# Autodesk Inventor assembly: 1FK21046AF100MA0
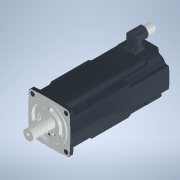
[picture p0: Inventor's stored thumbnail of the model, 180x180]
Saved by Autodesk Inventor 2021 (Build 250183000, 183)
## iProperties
Category: PARTsolutions
Created: 2026-06
Part Number: 1FK21046AF100MA0
Catalog Web Link: www.3dfindit.com
Description: 1FK21046AF100MA0-Servo synchronous motor
Document SubType Name: Assembly
Designer: psAdmin
Mass: 1063.44 g
Surface Area: 1248.48 cm^2
Volume: 1063.44 cm^3
Density: 1 g/cm^3
Title: 1FK21046AF100MA0
Author: Cadenas PARTsolutions
Comments: Servo synchronous motor
PSOL_IDENT_0: {$CADENAS_DATA/23d-libs/siemens_ag/_cat_/4f/2b/1fk21046af100ma0.prj},193 {STYP=ASS},{VTYP=3D},{NB=1F
PSOL_IDENT_1: K21046AF100MA0},{LINA=1FK21046AF100MA0},{NN=1FK21046AF100MA0},{DATE=19.08.2025 14:00:37},{GEOMDATE=3
PSOL_IDENT_2: 0.07.2025 02:01:06},{VERSION=},{LINEID=10},{WBVAR=},{WBNUMERIC=}  {NB=1FK21046AF100MA0},{LINA=1FK210
PSOL_IDENT_3: 46AF100MA0},{KT=DUMMY},{PREVIEW=../../../_pool_/cb/72/p_d211_xx_00434j.png},{DESCSHORT=SIMOTICS S-1F
PSOL_IDENT_4: K2 HD, SINAMICS S210 3AC 400V-480V, 3.2 Nm, 3000 rpm},{DESCLONG=SIMOTICS S-1FK2 HD servo motor M0=3.
PSOL_IDENT_5: 2 Nm; PN = 1 kW at nN=3000 rpm (380-480 V); PN = 0.5 kW at nN=1500 rpm (200-240 V); with holding bra
PSOL_IDENT_6: ke; degree of protection IP64; cylindrical shaft D19x40mm; absolute encoder 22-bit + 12-bit multitur
PSOL_IDENT_7: n (encoder AM22DQC); with OCC interface; plug size M17, rotatable; SIMOTICS S-1FK2 servomotorfor a w
PSOL_IDENT_8: ide range of uses in industrial environments. SIMOTICS S‑1FK2 servomotors are compact synchronous mo
PSOL_IDENT_9: tors with a high dynamic performance that set themselves apart as a result of their high power densi
PSOL_IDENT_10: ty, degree of protection and overload capability. The motors are available in two variants: as High
PSOL_IDENT_11: Dynamic variant (highest dynamic performance as a result of the low intrinsic moment of inertia for
PSOL_IDENT_12: applications demanding a high dynamic performance with low moved masses) - and as Compact variant (p
PSOL_IDENT_13: recise and stable closed-loop control for medium up to large moved masses as a result of a medium in
PSOL_IDENT_14: trinsic moment of inertia). SIMOTICSS‑1FK2 servomotors fully exploit their strengths in a system wit
PSOL_IDENT_15: h the SINAMICSS210 frequency converter and simple connection using the one cable connection (OCC). A
PSOL_IDENT_16: dvantages include the short control and positioning times, fast and precise correction of disturbing
PSOL_IDENT_17: quantities as well as stable control with a high dynamic performance. The servo motors can be confi
PSOL_IDENT_18: gured to address a wide range of requirements. For example with and without holding brake, IP64 or I
PSOL_IDENT_19: P65 degree of protection, singleturn or multiturn absolute encoders - to name just a few. Further, t
PSOL_IDENT_20: he servomotors are available in different shaft heights extending from 20 to 100. A shaft sealing ri
PSOL_IDENT_21: ng is available to achieve an IP65 degree of protection and for subsequent mounting at the motor or
PSOL_IDENT_22: as spare part. SIMOTICS - the optimum motor for each and every motion control application.},{INTNO=1
PSOL_IDENT_23: 95125049673},{SUPPLIERALTNO=1FK2104-6AF10-0MA0},{MANUID=1FK21046AF100MA0},{MANUNAME=Siemens},{MANUTY
PSOL_IDENT_24: PEDESC=Synchronous motor 1FK2-HD 3.2 NM},{AAU732=SIMOTICS},{AAO057=S-1FK2},{AAU734=SIMOTICS S-1FK2 H
PSOL_IDENT_25: D servo motor M0=3.2 Nm; PN = 1 kW at nN=3000 rpm (380-480 V); PN = 0.5 kW at nN=1500 rpm (200-240 V
PSOL_IDENT_26: ); with holding brake; degree of protection IP64; cylindrical shaft D19x40mm; absolute encoder 22-bi
PSOL_IDENT_27: t + 12-bit multiturn (encoder AM22DQC); with OCC interface; plug size M17, rotatable;},{AAW338=Synch
PSOL_IDENT_28: ronous motor 1FK2-HD 3.2 NM},{AAO742=SIMOTICS},{AAO663=4042948694534},{NOCUPEROU=1},{PRICEQUANTITY=1
PSOL_IDENT_29: },{QUANTITYMIN=1},{QUANTITYINT=1},{CTN=85015220},{COO=DE},{AAO676=1FK2104-6AF10-0MA0},{AAO677=Siemen
PSOL_IDENT_30: s AG},{ORDERUNIT=C62},{CONTENTUNIT=C62}
NB: 1FK21046AF100MA0
NN: 1FK21046AF100MA0
NT: Servo synchronous motor
NBSYN: $MANUID.
LINA: 1FK21046AF100MA0
CATALOG: SIEMENS
PREVIEW: ../../../_pool_/cb/72/p_d211_xx_00434j.png
DESCSHORT: SIMOTICS S-1FK2 HD, SINAMICS S210 3AC 400V-480V, 3.2 Nm, 3000 rpm
DESCLONG: SIMOTICS S-1FK2 HD servo motor M0=3.2 Nm; PN = 1 kW at nN=3000 rpm (380-480 V); PN = 0.5 kW at nN=1500 rpm (200-240 V); with holding brake; degree of protection
INTNO: 195125049673
SUPPLIERALTNO: 1FK2104-6AF10-0MA0
MANUID: 1FK21046AF100MA0
MANUNAME: Siemens
MANUTYPEDESC: Synchronous motor 1FK2-HD 3.2 NM
AAU732: SIMOTICS
AAO057: S-1FK2
AAU734: SIMOTICS S-1FK2 HD servo motor M0=3.2 Nm; PN = 1 kW at nN=3000 rpm (380-480 V); PN = 0.5 kW at nN=1500 rpm (200-240 V); with holding brake; degree of protection
AAW338: Synchronous motor 1FK2-HD 3.2 NM
AAO742: SIMOTICS
AAO663: 4042948694534.0
NOCUPEROU: 1
PRICEQUANTITY: 1
QUANTITYMIN: 1
QUANTITYINT: 1
CTN: 85015220
COO: DE
ARTICLENO: 1FK21046AF100MA0
BOMINFO: 1FK21046AF100MA0
CREATOR: CADENAS GmbH
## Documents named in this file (24)
- e:\temp\worker_COMMON_12\temp\tmp_2820_12_ZoeX4\format_0\1FK21046AF100MA0.iam
- e:\temp\worker_COMMON_12\temp\tmp_2820_12_ZoeX4\format_0\1FK21046AF100MA0_PART1.ipt
- e:\temp\worker_COMMON_12\temp\tmp_2820_12_ZoeX4\format_0\1FK21046AF100MA0_PART2.ipt
- e:\temp\worker_COMMON_12\temp\tmp_2820_12_ZoeX4\format_0\1FK21046AF100MA0_PART3.ipt
- e:\temp\worker_COMMON_12\temp\tmp_2820_12_ZoeX4\format_0\1FK21046AF100MA0_PART4.ipt
- e:\temp\worker_COMMON_12\temp\tmp_2820_12_ZoeX4\format_0\1FK21046AF100MA0_PART5.ipt
- e:\temp\worker_COMMON_12\temp\tmp_2820_12_ZoeX4\format_0\1FK21046AF100MA0_PART6.ipt
- e:\temp\worker_COMMON_12\temp\tmp_2820_12_ZoeX4\format_0\1FK21046AF100MA0_PART7.ipt
- e:\temp\worker_COMMON_12\temp\tmp_2820_12_ZoeX4\format_0\1FK21046AF100MA0_PART8.ipt
- e:\temp\worker_COMMON_12\temp\tmp_2820_12_ZoeX4\format_0\1FK21046AF100MA0_PART9.ipt
- e:\temp\worker_COMMON_12\temp\tmp_2820_12_ZoeX4\format_0\1FK21046AF100MA0_PART10.ipt
- e:\temp\worker_COMMON_12\temp\tmp_2820_12_ZoeX4\format_0\1FK21046AF100MA0_PART11.ipt
- e:\temp\worker_COMMON_12\temp\tmp_2820_12_ZoeX4\format_0\1FK21046AF100MA0_PART12.ipt
- e:\temp\worker_COMMON_12\temp\tmp_2820_12_ZoeX4\format_0\1FK21046AF100MA0_PART13.ipt
- e:\temp\worker_COMMON_12\temp\tmp_2820_12_ZoeX4\format_0\1FK21046AF100MA0_PART14.ipt
- e:\temp\worker_COMMON_12\temp\tmp_2820_12_ZoeX4\format_0\1FK21046AF100MA0_PART15.ipt
- e:\temp\worker_COMMON_12\temp\tmp_2820_12_ZoeX4\format_0\1FK21046AF100MA0_PART16.ipt
- e:\temp\worker_COMMON_12\temp\tmp_2820_12_ZoeX4\format_0\1FK21046AF100MA0_PART17.ipt
- e:\temp\worker_COMMON_12\temp\tmp_2820_12_ZoeX4\format_0\1FK21046AF100MA0_PART18.ipt
- e:\temp\worker_COMMON_12\temp\tmp_2820_12_ZoeX4\format_0\1FK21046AF100MA0_PART19.ipt
- e:\temp\worker_COMMON_12\temp\tmp_2820_12_ZoeX4\format_0\1FK21046AF100MA0_PART20.ipt
- e:\temp\worker_COMMON_12\temp\tmp_2820_12_ZoeX4\format_0\1FK21046AF100MA0_PART21.ipt
- e:\temp\worker_COMMON_12\temp\tmp_2820_12_ZoeX4\format_0\1FK21046AF100MA0_PART22.ipt
- e:\temp\worker_COMMON_12\temp\tmp_2820_12_ZoeX4\format_0\1FK21046AF100MA0_PART23.ipt
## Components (23 placed, 23 different names)
1. 1FK21046AF100MA0_PART1:1
2. 1FK21046AF100MA0_PART2:1
3. 1FK21046AF100MA0_PART3:1
4. 1FK21046AF100MA0_PART4:1
5. 1FK21046AF100MA0_PART5:1
6. 1FK21046AF100MA0_PART6:1
7. 1FK21046AF100MA0_PART7:1
8. 1FK21046AF100MA0_PART8:1
9. 1FK21046AF100MA0_PART9:1
10. 1FK21046AF100MA0_PART10:1
11. 1FK21046AF100MA0_PART11:1
12. 1FK21046AF100MA0_PART12:1
13. 1FK21046AF100MA0_PART13:1
14. 1FK21046AF100MA0_PART14:1
15. 1FK21046AF100MA0_PART15:1
16. 1FK21046AF100MA0_PART16:1
17. 1FK21046AF100MA0_PART17:1
18. 1FK21046AF100MA0_PART18:1
19. 1FK21046AF100MA0_PART19:1
20. 1FK21046AF100MA0_PART20:1
21. 1FK21046AF100MA0_PART21:1
22. 1FK21046AF100MA0_PART22:1
23. 1FK21046AF100MA0_PART23:1
